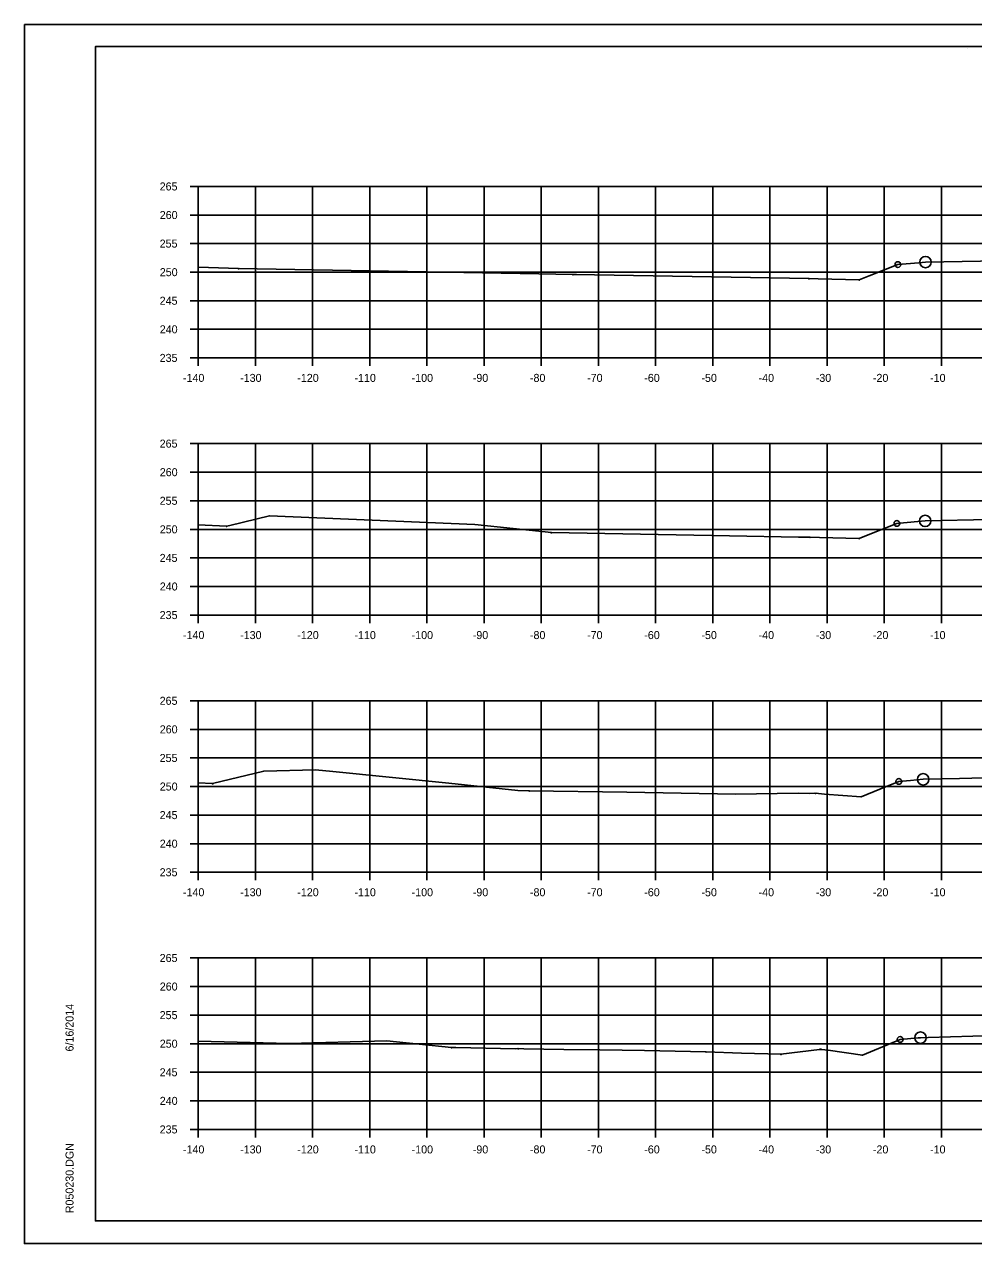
# Model space of a CAD drawing. Extents: x 1300404 to 1323571, y 234004 to 252077.
# Drawn here: x 1315546.9 to 1315712.9, y 244261.8 to 244475.2 of the extents above; entities that cross this region are included whole.
import ezdxf

# ---------------------------------------------------------------- set-up
doc = ezdxf.new("R2010")
doc.units = 0
for name, color, linetype in [('Default', 7, 'Continuous'), ('R_Axis', 7, 'Continuous'), ('R_Axis Annot', 7, 'Continuous'), ('R_Border', 7, 'Continuous'), ('R_Draft', 7, 'Continuous'), ('R_Exist Surface', 7, 'Continuous'), ('R_Grid', 7, 'Continuous'), ('R_No Plot', 7, 'Continuous')]:
    doc.layers.add(name, color=color, linetype=linetype)

msp = doc.modelspace()

# ---------------------------------------------------------------- linework, layer by layer
at = {"layer": 'Default'}
for p, q in [((1315559.28, 244471.28), (1315875.46, 244471.28)), ((1315559.28, 244265.82), (1315559.28, 244471.28)), ((1315875.46, 244265.82), (1315559.28, 244265.82))]:
    msp.add_line(p, q, dxfattribs=at)
at = {"layer": 'R_Axis'}
for p, q in [((1315575.88, 244446.82), (1315577.28, 244446.82)), ((1315577.28, 244416.82), (1315577.28, 244446.82)), ((1315575.88, 244441.82), (1315577.28, 244441.82)), ((1315575.88, 244436.82), (1315577.28, 244436.82)), ((1315575.88, 244431.82), (1315577.28, 244431.82)), ((1315575.88, 244426.82), (1315577.28, 244426.82)), ((1315575.88, 244421.82), (1315577.28, 244421.82)), ((1315575.88, 244416.82), (1315577.28, 244416.82)), ((1315577.28, 244416.82), (1315857.28, 244416.82)), ((1315577.28, 244415.42), (1315577.28, 244416.82)), ((1315587.28, 244415.42), (1315587.28, 244416.82)), ((1315597.28, 244415.42), (1315597.28, 244416.82)), ((1315607.28, 244415.42), (1315607.28, 244416.82)), ((1315617.28, 244415.42), (1315617.28, 244416.82)), ((1315627.28, 244415.42), (1315627.28, 244416.82)), ((1315637.28, 244415.42), (1315637.28, 244416.82)), ((1315647.28, 244415.42), (1315647.28, 244416.82)), ((1315657.28, 244415.42), (1315657.28, 244416.82)), ((1315667.28, 244415.42), (1315667.28, 244416.82)), ((1315677.28, 244415.42), (1315677.28, 244416.82)), ((1315687.28, 244415.42), (1315687.28, 244416.82)), ((1315697.28, 244415.42), (1315697.28, 244416.82)), ((1315707.28, 244415.42), (1315707.28, 244416.82)), ((1315575.88, 244401.82), (1315577.28, 244401.82)), ((1315577.28, 244371.82), (1315577.28, 244401.82)), ((1315575.88, 244396.82), (1315577.28, 244396.82)), ((1315575.88, 244391.82), (1315577.28, 244391.82)), ((1315575.88, 244386.82), (1315577.28, 244386.82)), ((1315575.88, 244381.82), (1315577.28, 244381.82)), ((1315575.88, 244376.82), (1315577.28, 244376.82)), ((1315575.88, 244371.82), (1315577.28, 244371.82)), ((1315577.28, 244371.82), (1315857.28, 244371.82)), ((1315577.28, 244370.42), (1315577.28, 244371.82)), ((1315587.28, 244370.42), (1315587.28, 244371.82)), ((1315597.28, 244370.42), (1315597.28, 244371.82)), ((1315607.28, 244370.42), (1315607.28, 244371.82)), ((1315617.28, 244370.42), (1315617.28, 244371.82)), ((1315627.28, 244370.42), (1315627.28, 244371.82)), ((1315637.28, 244370.42), (1315637.28, 244371.82)), ((1315647.28, 244370.42), (1315647.28, 244371.82)), ((1315657.28, 244370.42), (1315657.28, 244371.82)), ((1315667.28, 244370.42), (1315667.28, 244371.82)), ((1315677.28, 244370.42), (1315677.28, 244371.82)), ((1315687.28, 244370.42), (1315687.28, 244371.82)), ((1315697.28, 244370.42), (1315697.28, 244371.82)), ((1315707.28, 244370.42), (1315707.28, 244371.82)), ((1315575.88, 244356.82), (1315577.28, 244356.82)), ((1315577.28, 244326.82), (1315577.28, 244356.82)), ((1315575.88, 244351.82), (1315577.28, 244351.82)), ((1315575.88, 244346.82), (1315577.28, 244346.82)), ((1315575.88, 244341.82), (1315577.28, 244341.82)), ((1315575.88, 244336.82), (1315577.28, 244336.82)), ((1315575.88, 244331.82), (1315577.28, 244331.82)), ((1315575.88, 244326.82), (1315577.28, 244326.82)), ((1315577.28, 244326.82), (1315857.28, 244326.82)), ((1315577.28, 244325.42), (1315577.28, 244326.82)), ((1315587.28, 244325.42), (1315587.28, 244326.82)), ((1315597.28, 244325.42), (1315597.28, 244326.82)), ((1315607.28, 244325.42), (1315607.28, 244326.82)), ((1315617.28, 244325.42), (1315617.28, 244326.82)), ((1315627.28, 244325.42), (1315627.28, 244326.82)), ((1315637.28, 244325.42), (1315637.28, 244326.82)), ((1315647.28, 244325.42), (1315647.28, 244326.82)), ((1315657.28, 244325.42), (1315657.28, 244326.82)), ((1315667.28, 244325.42), (1315667.28, 244326.82)), ((1315677.28, 244325.42), (1315677.28, 244326.82)), ((1315687.28, 244325.42), (1315687.28, 244326.82)), ((1315697.28, 244325.42), (1315697.28, 244326.82)), ((1315707.28, 244325.42), (1315707.28, 244326.82)), ((1315575.88, 244311.82), (1315577.28, 244311.82)), ((1315577.28, 244281.82), (1315577.28, 244311.82)), ((1315575.88, 244306.82), (1315577.28, 244306.82)), ((1315575.88, 244301.82), (1315577.28, 244301.82)), ((1315575.88, 244296.82), (1315577.28, 244296.82)), ((1315575.88, 244291.82), (1315577.28, 244291.82)), ((1315575.88, 244286.82), (1315577.28, 244286.82)), ((1315575.88, 244281.82), (1315577.28, 244281.82)), ((1315577.28, 244281.82), (1315857.28, 244281.82)), ((1315577.28, 244280.42), (1315577.28, 244281.82)), ((1315587.28, 244280.42), (1315587.28, 244281.82)), ((1315597.28, 244280.42), (1315597.28, 244281.82)), ((1315607.28, 244280.42), (1315607.28, 244281.82)), ((1315617.28, 244280.42), (1315617.28, 244281.82)), ((1315627.28, 244280.42), (1315627.28, 244281.82)), ((1315637.28, 244280.42), (1315637.28, 244281.82)), ((1315647.28, 244280.42), (1315647.28, 244281.82)), ((1315657.28, 244280.42), (1315657.28, 244281.82)), ((1315667.28, 244280.42), (1315667.28, 244281.82)), ((1315677.28, 244280.42), (1315677.28, 244281.82)), ((1315687.28, 244280.42), (1315687.28, 244281.82)), ((1315697.28, 244280.42), (1315697.28, 244281.82)), ((1315707.28, 244280.42), (1315707.28, 244281.82))]:
    msp.add_line(p, q, dxfattribs=at)
at = {"layer": 'R_Border'}
for p, q in [((1315711.8, 244471.02), (1315711.8, 244471.02)), ((1315711.8, 244471.02), (1315711.8, 244471.02)), ((1315559.28, 244265.82), (1315559.28, 244265.82))]:
    msp.add_line(p, q, dxfattribs=at)
at = {"layer": 'R_Draft'}
for points in [[(1315584.32, 244432.5), (1315584.37, 244432.4), (1315584.27, 244432.4)], [(1315642.82, 244431.48), (1315642.87, 244431.38), (1315642.77, 244431.38)], [(1315684.14, 244430.74), (1315684.19, 244430.64), (1315684.09, 244430.64)], [(1315692.92, 244430.55), (1315692.97, 244430.45), (1315692.87, 244430.45)], [(1315582.24, 244387.42), (1315582.29, 244387.32), (1315582.19, 244387.32)], [(1315639.06, 244386.31), (1315639.11, 244386.21), (1315639.01, 244386.21)], [(1315684.3, 244385.52), (1315684.35, 244385.42), (1315684.25, 244385.42)], [(1315692.91, 244385.28), (1315692.96, 244385.18), (1315692.86, 244385.18)], [(1315579.79, 244342.37), (1315579.84, 244342.27), (1315579.74, 244342.27)], [(1315635.18, 244341.13), (1315635.23, 244341.03), (1315635.13, 244341.03)], [(1315685.28, 244340.72), (1315685.33, 244340.62), (1315685.23, 244340.62)], [(1315693.25, 244340.09), (1315693.3, 244339.99), (1315693.2, 244339.99)], [(1315621.57, 244296.2), (1315621.62, 244296.1), (1315621.52, 244296.1)], [(1315633.28, 244296.01), (1315633.33, 244295.91), (1315633.23, 244295.91)], [(1315666.11, 244295.44), (1315666.16, 244295.34), (1315666.06, 244295.34)], [(1315686.15, 244295.92), (1315686.2, 244295.82), (1315686.1, 244295.82)], [(1315679.21, 244295.02), (1315679.26, 244294.92), (1315679.16, 244294.92)], [(1315693.46, 244294.89), (1315693.51, 244294.79), (1315693.41, 244294.79)]]:
    msp.add_lwpolyline(points, close=True, dxfattribs=at)
at = {"layer": 'R_Exist Surface'}
for points in [[(1315577.28, 244432.71), (1315577.31, 244432.71), (1315584.32, 244432.45), (1315636.85, 244431.53), (1315642.82, 244431.43), (1315643.45, 244431.42), (1315646.62, 244431.36), (1315684.14, 244430.69), (1315685.71, 244430.66), (1315692.92, 244430.5), (1315694.67, 244431.17), (1315699.69, 244433.14), (1315703.35, 244433.48), (1315704.51, 244433.59), (1315707.71, 244433.64), (1315717.34, 244433.83)], [(1315577.28, 244387.61), (1315582.24, 244387.37), (1315582.78, 244387.5), (1315589.72, 244389.21), (1315625.68, 244387.64), (1315639.06, 244386.26), (1315670.23, 244385.66), (1315682.29, 244385.45), (1315684.3, 244385.47), (1315685.98, 244385.37), (1315692.91, 244385.23), (1315693.59, 244385.5), (1315699.5, 244387.86), (1315700.02, 244387.9), (1315704.45, 244388.29), (1315715.7, 244388.54)], [(1315577.28, 244342.46), (1315579.79, 244342.32), (1315588.74, 244344.52), (1315597.79, 244344.76), (1315600.8, 244344.45), (1315621.13, 244342.39), (1315633.18, 244341.12), (1315635.18, 244341.08), (1315652.28, 244340.84), (1315671.3, 244340.5), (1315682.22, 244340.63), (1315684.19, 244340.58), (1315685.28, 244340.67), (1315686.85, 244340.51), (1315693.25, 244340.04), (1315696.51, 244341.37), (1315699.84, 244342.71), (1315701.89, 244342.89), (1315704.1, 244343.08), (1315710.45, 244343.24), (1315717.01, 244343.41)], [(1315577.28, 244297.26), (1315593.18, 244296.88), (1315610.25, 244297.35), (1315621.57, 244296.15), (1315622.33, 244296.14), (1315632.77, 244295.94), (1315633.28, 244295.96), (1315634.25, 244295.93), (1315641.25, 244295.82), (1315647.56, 244295.76), (1315655.33, 244295.64), (1315666.11, 244295.39), (1315672.34, 244295.18), (1315679.21, 244294.97), (1315685.94, 244295.83), (1315686.15, 244295.87), (1315686.34, 244295.83), (1315687.5, 244295.67), (1315693.46, 244294.84), (1315699.35, 244297.28), (1315700.06, 244297.57), (1315703.22, 244297.84), (1315703.63, 244297.87), (1315705, 244297.91), (1315716.71, 244298.26)]]:
    msp.add_lwpolyline(points, dxfattribs=at)
at = {"layer": 'R_Grid'}
for p, q in [((1315577.28, 244446.82), (1315857.28, 244446.82)), ((1315577.28, 244416.82), (1315577.28, 244446.82)), ((1315587.28, 244416.82), (1315587.28, 244446.82)), ((1315597.28, 244416.82), (1315597.28, 244446.82)), ((1315607.28, 244416.82), (1315607.28, 244446.82)), ((1315617.28, 244416.82), (1315617.28, 244446.82)), ((1315627.28, 244416.82), (1315627.28, 244446.82)), ((1315637.28, 244416.82), (1315637.28, 244446.82)), ((1315647.28, 244416.82), (1315647.28, 244446.82)), ((1315657.28, 244416.82), (1315657.28, 244446.82)), ((1315667.28, 244416.82), (1315667.28, 244446.82)), ((1315677.28, 244416.82), (1315677.28, 244446.82)), ((1315687.28, 244416.82), (1315687.28, 244446.82)), ((1315697.28, 244416.82), (1315697.28, 244446.82)), ((1315707.28, 244416.82), (1315707.28, 244446.82)), ((1315577.28, 244441.82), (1315857.28, 244441.82)), ((1315577.28, 244436.82), (1315857.28, 244436.82)), ((1315577.28, 244431.82), (1315857.28, 244431.82)), ((1315577.28, 244426.82), (1315857.28, 244426.82)), ((1315577.28, 244421.82), (1315857.28, 244421.82)), ((1315577.28, 244416.82), (1315857.28, 244416.82)), ((1315577.28, 244401.82), (1315857.28, 244401.82)), ((1315577.28, 244371.82), (1315577.28, 244401.82)), ((1315587.28, 244371.82), (1315587.28, 244401.82)), ((1315597.28, 244371.82), (1315597.28, 244401.82)), ((1315607.28, 244371.82), (1315607.28, 244401.82)), ((1315617.28, 244371.82), (1315617.28, 244401.82)), ((1315627.28, 244371.82), (1315627.28, 244401.82)), ((1315637.28, 244371.82), (1315637.28, 244401.82)), ((1315647.28, 244371.82), (1315647.28, 244401.82)), ((1315657.28, 244371.82), (1315657.28, 244401.82)), ((1315667.28, 244371.82), (1315667.28, 244401.82)), ((1315677.28, 244371.82), (1315677.28, 244401.82)), ((1315687.28, 244371.82), (1315687.28, 244401.82)), ((1315697.28, 244371.82), (1315697.28, 244401.82)), ((1315707.28, 244371.82), (1315707.28, 244401.82)), ((1315577.28, 244396.82), (1315857.28, 244396.82)), ((1315577.28, 244391.82), (1315857.28, 244391.82)), ((1315577.28, 244386.82), (1315857.28, 244386.82)), ((1315577.28, 244381.82), (1315857.28, 244381.82)), ((1315577.28, 244376.82), (1315857.28, 244376.82)), ((1315577.28, 244371.82), (1315857.28, 244371.82)), ((1315577.28, 244356.82), (1315857.28, 244356.82)), ((1315577.28, 244326.82), (1315577.28, 244356.82)), ((1315587.28, 244326.82), (1315587.28, 244356.82)), ((1315597.28, 244326.82), (1315597.28, 244356.82)), ((1315607.28, 244326.82), (1315607.28, 244356.82)), ((1315617.28, 244326.82), (1315617.28, 244356.82)), ((1315627.28, 244326.82), (1315627.28, 244356.82)), ((1315637.28, 244326.82), (1315637.28, 244356.82)), ((1315647.28, 244326.82), (1315647.28, 244356.82)), ((1315657.28, 244326.82), (1315657.28, 244356.82)), ((1315667.28, 244326.82), (1315667.28, 244356.82)), ((1315677.28, 244326.82), (1315677.28, 244356.82)), ((1315687.28, 244326.82), (1315687.28, 244356.82)), ((1315697.28, 244326.82), (1315697.28, 244356.82)), ((1315707.28, 244326.82), (1315707.28, 244356.82)), ((1315577.28, 244351.82), (1315857.28, 244351.82)), ((1315577.28, 244346.82), (1315857.28, 244346.82)), ((1315577.28, 244341.82), (1315857.28, 244341.82)), ((1315577.28, 244336.82), (1315857.28, 244336.82)), ((1315577.28, 244331.82), (1315857.28, 244331.82)), ((1315577.28, 244326.82), (1315857.28, 244326.82)), ((1315577.28, 244311.82), (1315857.28, 244311.82)), ((1315577.28, 244281.82), (1315577.28, 244311.82)), ((1315587.28, 244281.82), (1315587.28, 244311.82)), ((1315597.28, 244281.82), (1315597.28, 244311.82)), ((1315607.28, 244281.82), (1315607.28, 244311.82)), ((1315617.28, 244281.82), (1315617.28, 244311.82)), ((1315627.28, 244281.82), (1315627.28, 244311.82)), ((1315637.28, 244281.82), (1315637.28, 244311.82)), ((1315647.28, 244281.82), (1315647.28, 244311.82)), ((1315657.28, 244281.82), (1315657.28, 244311.82)), ((1315667.28, 244281.82), (1315667.28, 244311.82)), ((1315677.28, 244281.82), (1315677.28, 244311.82)), ((1315687.28, 244281.82), (1315687.28, 244311.82)), ((1315697.28, 244281.82), (1315697.28, 244311.82)), ((1315707.28, 244281.82), (1315707.28, 244311.82)), ((1315577.28, 244306.82), (1315857.28, 244306.82)), ((1315577.28, 244301.82), (1315857.28, 244301.82)), ((1315577.28, 244296.82), (1315857.28, 244296.82)), ((1315577.28, 244291.82), (1315857.28, 244291.82)), ((1315577.28, 244286.82), (1315857.28, 244286.82)), ((1315577.28, 244281.82), (1315857.28, 244281.82))]:
    msp.add_line(p, q, dxfattribs=at)
at = {"layer": 'R_No Plot'}
for p, q in [((1315546.87, 244475.18), (1315880.21, 244475.18)), ((1315546.87, 244261.84), (1315880.21, 244261.84))]:
    msp.add_line(p, q, dxfattribs=at)
for points in [[(1315546.87, 244475.18), (1315880.21, 244475.18), (1315880.21, 244261.84), (1315546.87, 244261.84)], [(1315793.2, 244471.28), (1315793.2, 244461.4), (1315828.93, 244461.4), (1315828.93, 244458.48), (1315852.13, 244458.48), (1315852.13, 244436.36), (1315875.46, 244436.36), (1315875.46, 244265.82), (1315559.28, 244265.82), (1315559.28, 244471.28)]]:
    msp.add_lwpolyline(points, close=True, dxfattribs=at)
for centre, radius in [((1315704.51, 244433.59), 1), ((1315699.69, 244433.14), 0.5), ((1315704.45, 244388.29), 1), ((1315699.5, 244387.86), 0.5), ((1315699.84, 244342.71), 0.5), ((1315704.1, 244343.08), 1), ((1315700.06, 244297.57), 0.5), ((1315703.63, 244297.87), 1)]:
    msp.add_circle(centre, radius, dxfattribs=at)

# ---------------------------------------------------------------- texts
at = {"layer": 'R_Axis'}
for p in [(1315577.28, 244416.82), (1315577.28, 244371.82), (1315577.28, 244326.82), (1315577.28, 244281.82)]:
    msp.add_text('-', height=0.0001, dxfattribs=at).set_placement(p)
at = {"layer": 'R_Axis Annot'}
for s, p in [('265', (1315570.53, 244446.12)), ('260', (1315570.55, 244441.12)), ('255', (1315570.53, 244436.12)), ('250', (1315570.55, 244431.12)), ('245', (1315570.53, 244426.12)), ('240', (1315570.55, 244421.12)), ('235', (1315570.53, 244416.12)), ('-140', (1315574.61, 244412.62)), ('-130', (1315584.61, 244412.62)), ('-120', (1315594.61, 244412.62)), ('-110', (1315604.61, 244412.62)), ('-100', (1315614.61, 244412.62)), ('-90', (1315625.31, 244412.62)), ('-80', (1315635.31, 244412.62)), ('-70', (1315645.31, 244412.62)), ('-60', (1315655.31, 244412.62)), ('-50', (1315665.31, 244412.62)), ('-40', (1315675.31, 244412.62)), ('-30', (1315685.31, 244412.62)), ('-20', (1315695.31, 244412.62)), ('-10', (1315705.31, 244412.62)), ('265', (1315570.53, 244401.12)), ('260', (1315570.55, 244396.12)), ('255', (1315570.53, 244391.12)), ('250', (1315570.55, 244386.12)), ('245', (1315570.53, 244381.12)), ('240', (1315570.55, 244376.12)), ('235', (1315570.53, 244371.12)), ('-140', (1315574.61, 244367.62)), ('-130', (1315584.61, 244367.62)), ('-120', (1315594.61, 244367.62)), ('-110', (1315604.61, 244367.62)), ('-100', (1315614.61, 244367.62)), ('-90', (1315625.31, 244367.62)), ('-80', (1315635.31, 244367.62)), ('-70', (1315645.31, 244367.62)), ('-60', (1315655.31, 244367.62)), ('-50', (1315665.31, 244367.62)), ('-40', (1315675.31, 244367.62)), ('-30', (1315685.31, 244367.62)), ('-20', (1315695.31, 244367.62)), ('-10', (1315705.31, 244367.62)), ('265', (1315570.53, 244356.12)), ('260', (1315570.55, 244351.12)), ('255', (1315570.53, 244346.12)), ('250', (1315570.55, 244341.12)), ('245', (1315570.53, 244336.12)), ('240', (1315570.55, 244331.12)), ('235', (1315570.53, 244326.12)), ('-140', (1315574.61, 244322.62)), ('-130', (1315584.61, 244322.62)), ('-120', (1315594.61, 244322.62)), ('-110', (1315604.61, 244322.62)), ('-100', (1315614.61, 244322.62)), ('-90', (1315625.31, 244322.62)), ('-80', (1315635.31, 244322.62)), ('-70', (1315645.31, 244322.62)), ('-60', (1315655.31, 244322.62)), ('-50', (1315665.31, 244322.62)), ('-40', (1315675.31, 244322.62)), ('-30', (1315685.31, 244322.62)), ('-20', (1315695.31, 244322.62)), ('-10', (1315705.31, 244322.62)), ('265', (1315570.53, 244311.12)), ('260', (1315570.55, 244306.12)), ('255', (1315570.53, 244301.12)), ('250', (1315570.55, 244296.12)), ('245', (1315570.53, 244291.12)), ('240', (1315570.55, 244286.12)), ('235', (1315570.53, 244281.12)), ('-140', (1315574.61, 244277.62)), ('-130', (1315584.61, 244277.62)), ('-120', (1315594.61, 244277.62)), ('-110', (1315604.61, 244277.62)), ('-100', (1315614.61, 244277.62)), ('-90', (1315625.31, 244277.62)), ('-80', (1315635.31, 244277.62)), ('-70', (1315645.31, 244277.62)), ('-60', (1315655.31, 244277.62)), ('-50', (1315665.31, 244277.62)), ('-40', (1315675.31, 244277.62)), ('-30', (1315685.31, 244277.62)), ('-20', (1315695.31, 244277.62)), ('-10', (1315705.31, 244277.62))]:
    msp.add_text(s, height=1.4, dxfattribs=at).set_placement(p)
at = {"layer": 'R_Border'}
for s, p in [('6/16/2014', (1315555.47, 244295.46)), ('R050230.DGN', (1315555.47, 244267.15))]:
    msp.add_text(s, height=1.4, rotation=90, dxfattribs=at).set_placement(p)

doc.saveas('drawing.dxf')
